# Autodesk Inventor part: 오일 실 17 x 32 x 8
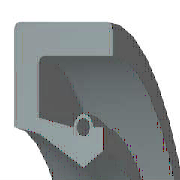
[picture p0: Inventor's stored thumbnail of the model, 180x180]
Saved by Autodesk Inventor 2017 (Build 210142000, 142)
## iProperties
IsCustomPart: 1
Created: 2012-02
Part Number: 오일 실 17 x 32 x 8
Material: 고무
Description: 오일-실
Document SubType Name: Modeling
Standard: KS B 2804
Designer: test
Standards Organization: KS
Language: ko-KR
Size Designation: S - 17 32 8
Categories: <MemberInstance><Categories><Category DisplayName="샤프트 부품" InternalName="7f7aeb1f-a693-4053-b835-cee3144e0d98" Mnemonic="SHFT"><Category DisplayName="실링" Intern
Density: 0.93 g/cm^3
Appearance: 고무 - 검은색 - 버전 1.1
Author: test
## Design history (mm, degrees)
revolve "본체" stored, may be unused: angle "d17" = 90 deg
revolve "스프링1" stored, may be unused: angle "d18" = 90 deg
body "Solid1"
sketch "스케치1"
  geometry: L1 (0, 16)-(8, 16); L2 (8, 16)-(8, 14.75); L3 (8, 14.75)-(1.75, 14.75); L4 (0, 16)-(0, 10.6); L5 (0, 10.6)-(1.75, 10.25); L6 (1.75, 10.25)-(4.9, 8.5); L7 (4.9, 8.5)-(0, 8.5); L8 (6.3, 9.375)-(6.3, 10.6); L9 (0, 0)-(9.586, 0) reference; L10 (4.9, 8.5)-(6.3, 9.375); L11 (0, 18)-(0, -3) reference; L12 (-1.917, 0)-(11.503, 0) reference; L13 (4.2, 10.6)-(1.75, 11.09); L14 (1.75, 11.09)-(1.75, 14.75); L15 (6.3, 10.6)-(5.6, 10.6); C1 r 0.455 at (4.9, 10.6); A1 r 0.7 centre (4.9, 10.6) between (5.6, 10.6) and (4.2, 10.6)
  constraints: 26 end point, 5 horizontal alignment, 4 perpendicular, 2 centre point, 2 collinear, 2 horizontal, 2 parallel, 2 point on circle, 2 point on line, 2 vertical alignment, 1 coincident
  dimensions: "d0" = 32 diameter of L1 L9 (= SD2); "d1" = 18.75 diameter of L8.start L9 (= ABDM); "d2" = 1.25 distance of L1.end L2.end (computed from SD); "d3" = 0.91 diameter of C1 (= SPDI); "d4" = 1.4 diameter of A1 (= SPDA); "d5" = 17 diameter of L6.end L9 (= NND); "d6" = 20.5 diameter of L5.end L9 (= TKDM); "d7" = 21.2 diameter of L4.end L9 (= HLDM); "d8" = 4.9 distance from line of C1.centre L4 (= SPDST); "d9" = 6.3 distance between parallel lines of L8 L4 (= SDI); "d10" = 8 distance between parallel lines of L2 L4 (= SWDT); "d12" = 1.75 distance between parallel lines of L14 L4 (= SD)
fillet "모깎기1" dims "d11" = 0.3 (= RR)
other parameters: "SD2" = 32 [user parameter; used in 1 equation term], "SWDT" = 8 [user parameter; used in 1 equation term], "RR" = 0.3 [user parameter; used in 1 equation term], "SD" = 1.75 [user parameter; used in 2 equation terms], "NND" = 17 [user parameter; used in 1 equation term], "SPDA" = 1.4 [user parameter; used in 1 equation term], "SPDI" = 0.91 [user parameter; used in 1 equation term], "TKDM" = 20.5 [user parameter; used in 1 equation term], "HLDM" = 21.2 [user parameter; used in 1 equation term], "ABDM" = 18.75 [user parameter; used in 1 equation term], "SDI" = 6.3 [user parameter; used in 1 equation term], "SPDST" = 4.9 [user parameter; used in 1 equation term], "d13" = 0, "d14" = 0, "d15" = 0, "LAB" = 0.35 [user parameter]
